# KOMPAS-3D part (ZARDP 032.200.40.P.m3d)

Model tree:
1. Булева операция:2
2. Булева операция:3
3. Булева операция:4
4. Булева операция:5
5. Булева операция:6
6. Булева операция:7
7. Булева операция:8
8. Булева операция:9
9. Булева операция:10
10. Булева операция:11
11. Булева операция:12
12. Булева операция:13
13. Булева операция:14
14. Булева операция:15
15. Булева операция:16
16. Булева операция:17
17. Булева операция:18
18. Булева операция:19
19. Булева операция:20
20. Булева операция:21
21. Булева операция:22
22. Булева операция:23

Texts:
  ООО ИК Энерпред-Ярдос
